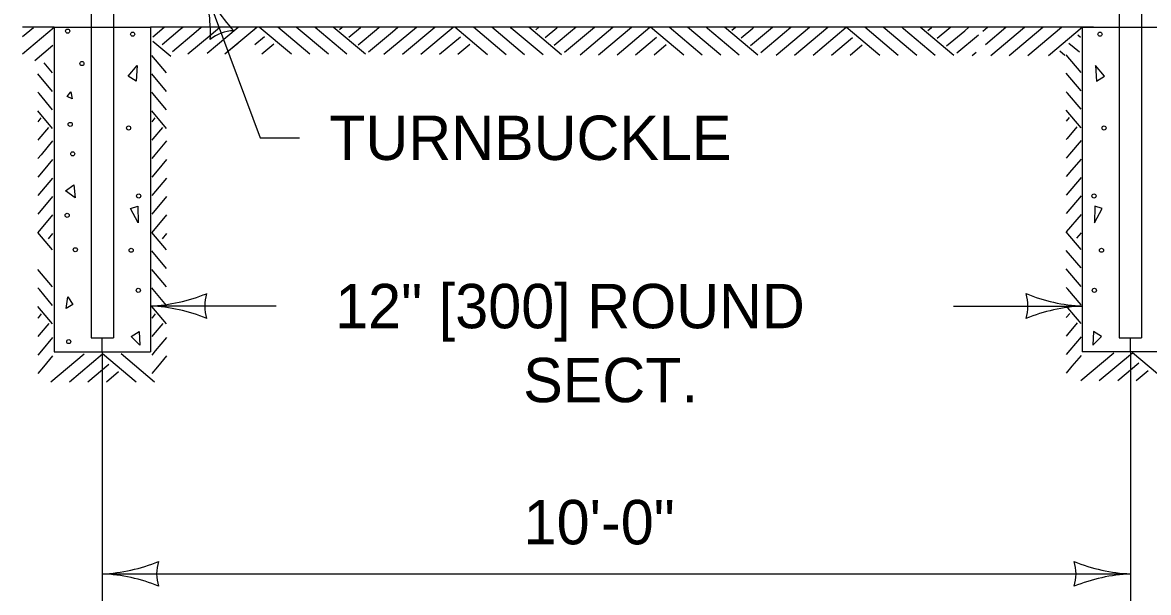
# Model space of a CAD drawing. Extents: x 49973.1 to 50021, y 49987.6 to 50015.4.
# Drawn here: x 50000.781 to 50002.303, y 49991.647 to 49992.418 of the extents above; entities that cross this region are included whole.
import ezdxf

# ---------------------------------------------------------------- set-up
doc = ezdxf.new("R2010")
doc.units = 0
for name, color, linetype in [('Level 1', 7, 'Continuous'), ('Level 2', 7, 'Continuous'), ('Level 3', 7, 'Continuous')]:
    doc.layers.add(name, color=color, linetype=linetype)

msp = doc.modelspace()

# ---------------------------------------------------------------- linework, layer by layer
at = {"layer": 'Level 1'}
for p, q in [((50000.8737, 49992.4466), (50000.8737, 49991.9918)), ((50000.9037, 49992.4466), (50000.9037, 49991.9918)), ((50002.2634, 49992.4418), (50002.2634, 49991.9918)), ((50002.2934, 49992.4418), (50002.2934, 49991.9918)), ((50000.7808, 49992.3757), (50000.8237, 49992.4117)), ((50000.8237, 49992.4117), (50000.7808, 49992.4117)), ((50000.7808, 49992.3992), (50000.7955, 49992.4116)), ((50000.8237, 49992.4118), (50000.8237, 49991.9727)), ((50000.8237, 49992.4118), (50000.9537, 49992.4118)), ((50000.8314, 49992.4117), (50000.8337, 49992.4117)), ((50002.2284, 49992.4118), (50000.9537, 49992.4118)), ((50000.9537, 49992.4118), (50000.9537, 49991.9727)), ((50000.957, 49992.3989), (50000.9724, 49992.4117)), ((50000.9941, 49992.409), (50000.9974, 49992.4117)), ((50001.0157, 49992.4061), (50001.0225, 49992.4117)), ((50001.0304, 49992.3765), (50001.0725, 49992.4117)), ((50001.0358, 49992.4019), (50001.0475, 49992.4117)), ((50001.0543, 49992.3756), (50001.0974, 49992.4117)), ((50001.0917, 49992.4069), (50001.0974, 49992.4117)), ((50001.1444, 49992.3751), (50001.1009, 49992.4117)), ((50001.1694, 49992.3751), (50001.1259, 49992.4117)), ((50001.1944, 49992.3751), (50001.1509, 49992.4117)), ((50001.1764, 49992.4112), (50001.1759, 49992.4117)), ((50001.2194, 49992.3751), (50001.1764, 49992.4112)), ((50001.2444, 49992.3751), (50001.2009, 49992.4117)), ((50001.2094, 49992.4086), (50001.2131, 49992.4117)), ((50001.2221, 49992.3984), (50001.2378, 49992.4115)), ((50001.2378, 49992.4115), (50001.2381, 49992.4117)), ((50001.2592, 49992.4085), (50001.2631, 49992.4117)), ((50001.2694, 49992.3751), (50001.3132, 49992.4117)), ((50001.2808, 49992.4056), (50001.2882, 49992.4117)), ((50001.2944, 49992.3751), (50001.3382, 49992.4117)), ((50001.3194, 49992.3751), (50001.3631, 49992.4117)), ((50001.4095, 49992.3746), (50001.3654, 49992.4117)), ((50001.4345, 49992.3746), (50001.3904, 49992.4117)), ((50001.4595, 49992.3746), (50001.4154, 49992.4117)), ((50001.4415, 49992.4107), (50001.4404, 49992.4117)), ((50001.4845, 49992.3746), (50001.4415, 49992.4107)), ((50001.5095, 49992.3746), (50001.4654, 49992.4117)), ((50001.4745, 49992.4081), (50001.4788, 49992.4117)), ((50001.4872, 49992.3979), (50001.5029, 49992.411)), ((50001.5029, 49992.411), (50001.5038, 49992.4117)), ((50001.5243, 49992.408), (50001.5288, 49992.4117)), ((50001.5345, 49992.3746), (50001.5789, 49992.4117)), ((50001.5459, 49992.4051), (50001.5539, 49992.4117)), ((50001.5595, 49992.3746), (50001.6039, 49992.4117)), ((50001.5845, 49992.3746), (50001.6288, 49992.4117)), ((50001.6746, 49992.3741), (50001.6299, 49992.4117)), ((50001.6996, 49992.3741), (50001.6549, 49992.4117)), ((50001.7246, 49992.3741), (50001.6799, 49992.4117)), ((50001.7066, 49992.4102), (50001.7049, 49992.4117)), ((50001.7496, 49992.3741), (50001.7066, 49992.4102)), ((50001.7746, 49992.3741), (50001.7299, 49992.4117)), ((50001.7396, 49992.4076), (50001.7446, 49992.4118)), ((50001.7523, 49992.3974), (50001.768, 49992.4105)), ((50001.768, 49992.4105), (50001.7695, 49992.4117)), ((50001.7894, 49992.4075), (50001.7945, 49992.4117)), ((50001.7996, 49992.3741), (50001.8446, 49992.4117)), ((50001.811, 49992.4046), (50001.8196, 49992.4117)), ((50001.8246, 49992.3741), (50001.8696, 49992.4117)), ((50001.8496, 49992.3741), (50001.8944, 49992.4117)), ((50001.9397, 49992.3736), (50001.8944, 49992.4117)), ((50001.9647, 49992.3736), (50001.9194, 49992.4117)), ((50001.9897, 49992.3736), (50001.9444, 49992.4117)), ((50001.9717, 49992.4097), (50001.9694, 49992.4117)), ((50002.0147, 49992.3736), (50001.9717, 49992.4097)), ((50002.0397, 49992.3736), (50001.9944, 49992.4117)), ((50002.0047, 49992.4071), (50002.0097, 49992.4113)), ((50002.0097, 49992.4113), (50002.0102, 49992.4117)), ((50002.0174, 49992.3969), (50002.0331, 49992.41)), ((50002.0331, 49992.41), (50002.0352, 49992.4117)), ((50002.0545, 49992.407), (50002.0602, 49992.4117)), ((50002.0788, 49992.4064), (50002.0853, 49992.4117)), ((50002.0825, 49992.3885), (50002.1102, 49992.4117)), ((50002.0897, 49992.3736), (50002.1352, 49992.4117)), ((50002.1147, 49992.3736), (50002.1601, 49992.4117)), ((50002.1397, 49992.3736), (50002.1852, 49992.4117)), ((50002.1679, 49992.3737), (50002.2134, 49992.4118)), ((50002.2134, 49992.4118), (50002.2134, 49991.9727)), ((50002.2134, 49992.4118), (50002.3434, 49992.4118)), ((50000.9695, 49992.3884), (50000.9941, 49992.409)), ((50000.9834, 49992.379), (50001.0157, 49992.4061)), ((50001.0043, 49992.3756), (50001.0358, 49992.4019)), ((50001.0948, 49992.3886), (50001.1077, 49992.3994)), ((50001.2346, 49992.3879), (50001.2592, 49992.4085)), ((50001.2485, 49992.3785), (50001.2808, 49992.4056)), ((50001.3444, 49992.3751), (50001.3728, 49992.3989)), ((50001.4997, 49992.3874), (50001.5243, 49992.408)), ((50001.5136, 49992.378), (50001.5459, 49992.4051)), ((50001.6095, 49992.3746), (50001.6379, 49992.3984)), ((50001.7648, 49992.3869), (50001.7894, 49992.4075)), ((50001.7787, 49992.3775), (50001.811, 49992.4046)), ((50001.8746, 49992.3741), (50001.903, 49992.3979)), ((50002.0299, 49992.3864), (50002.0545, 49992.407)), ((50002.0438, 49992.377), (50002.0731, 49992.4016)), ((50002.2108, 49992.3979), (50002.2073, 49992.4008)), ((50000.7974, 49992.3667), (50000.822, 49992.3873)), ((50000.9814, 49992.372), (50000.9568, 49992.3926)), ((50001.0543, 49992.3756), (50001.0717, 49992.3902)), ((50001.1043, 49992.3756), (50001.1206, 49992.3893)), ((50001.3694, 49992.3751), (50001.3857, 49992.3888)), ((50001.6345, 49992.3746), (50001.6508, 49992.3883)), ((50001.8996, 49992.3741), (50001.9159, 49992.3878)), ((50002.1897, 49992.3736), (50002.1829, 49992.3793)), ((50002.2096, 49992.3779), (50002.1952, 49992.3899)), ((50000.8215, 49992.35), (50000.81, 49992.3637)), ((50000.9755, 49992.35), (50000.9556, 49992.3737)), ((50002.0647, 49992.3736), (50002.07, 49992.3781)), ((50002.2117, 49992.3507), (50002.1918, 49992.3744)), ((50000.8215, 49992.325), (50000.8016, 49992.3487)), ((50000.9755, 49992.325), (50000.9556, 49992.3487)), ((50002.2117, 49992.3257), (50002.1918, 49992.3494)), ((50000.8031, 49992.322), (50000.8016, 49992.3237)), ((50000.8215, 49992.3), (50000.8031, 49992.322)), ((50000.9571, 49992.322), (50000.9556, 49992.3237)), ((50000.9755, 49992.3), (50000.9571, 49992.322)), ((50002.1933, 49992.3227), (50002.1918, 49992.3244)), ((50002.2117, 49992.3007), (50002.1933, 49992.3227)), ((50000.8057, 49992.289), (50000.8015, 49992.284)), ((50000.8215, 49992.275), (50000.8016, 49992.2987)), ((50000.9597, 49992.289), (50000.9555, 49992.284)), ((50000.9755, 49992.275), (50000.9556, 49992.2987)), ((50002.1959, 49992.2897), (50002.1917, 49992.2847)), ((50002.2117, 49992.2757), (50002.1918, 49992.2994)), ((50000.8159, 49992.2763), (50000.8028, 49992.2606)), ((50000.9699, 49992.2763), (50000.9568, 49992.2606)), ((50002.2061, 49992.277), (50002.193, 49992.2613)), ((50000.8028, 49992.2606), (50000.8016, 49992.2591)), ((50000.8215, 49992.2579), (50000.8058, 49992.2392)), ((50000.9568, 49992.2606), (50000.9556, 49992.2591)), ((50000.9755, 49992.2579), (50000.9598, 49992.2392)), ((50002.193, 49992.2613), (50002.1918, 49992.2598)), ((50002.2117, 49992.2586), (50002.196, 49992.2399)), ((50000.8058, 49992.2392), (50000.8016, 49992.2341)), ((50000.8215, 49992.2328), (50000.8087, 49992.2176)), ((50000.9598, 49992.2392), (50000.9556, 49992.2341)), ((50000.9755, 49992.2328), (50000.9627, 49992.2176)), ((50002.196, 49992.2399), (50002.1918, 49992.2348)), ((50002.2117, 49992.2335), (50002.1989, 49992.2183)), ((50000.8087, 49992.2176), (50000.8016, 49992.209)), ((50000.9627, 49992.2176), (50000.9556, 49992.209)), ((50002.1989, 49992.2183), (50002.1918, 49992.2097)), ((50000.8215, 49992.2078), (50000.8016, 49992.184)), ((50000.9755, 49992.2078), (50000.9556, 49992.184)), ((50002.2117, 49992.2085), (50002.1918, 49992.1847)), ((50000.8215, 49992.1828), (50000.8016, 49992.159)), ((50000.9755, 49992.1828), (50000.9556, 49992.159)), ((50002.2117, 49992.1835), (50002.1918, 49992.1597)), ((50000.8215, 49992.1579), (50000.8016, 49992.1342)), ((50000.9755, 49992.1579), (50000.9556, 49992.1342)), ((50002.2117, 49992.1586), (50002.1918, 49992.1349)), ((50000.8215, 49992.1105), (50000.8016, 49992.1342)), ((50000.8215, 49992.1328), (50000.8154, 49992.1256)), ((50000.9755, 49992.1105), (50000.9556, 49992.1342)), ((50000.9755, 49992.1328), (50000.9694, 49992.1256)), ((50002.2117, 49992.1112), (50002.1918, 49992.1349)), ((50002.2117, 49992.1335), (50002.2056, 49992.1263)), ((50000.9755, 49992.0855), (50000.9556, 49992.1092)), ((50002.2117, 49992.0862), (50002.1918, 49992.1099)), ((50000.8215, 49992.0605), (50000.8016, 49992.0842)), ((50000.9755, 49992.0605), (50000.9556, 49992.0842)), ((50002.2117, 49992.0612), (50002.1918, 49992.0849)), ((50000.8036, 49992.0569), (50000.8016, 49992.0592)), ((50000.9576, 49992.0569), (50000.9556, 49992.0592)), ((50002.1938, 49992.0576), (50002.1918, 49992.0599)), ((50000.8215, 49992.0355), (50000.8036, 49992.0569)), ((50000.9755, 49992.0355), (50000.9576, 49992.0569)), ((50002.2117, 49992.0362), (50002.1938, 49992.0576)), ((50000.8215, 49992.0105), (50000.8016, 49992.0342)), ((50000.9755, 49992.0105), (50000.9556, 49992.0342)), ((50002.2117, 49992.0112), (50002.1918, 49992.0349)), ((50000.802, 49992.0189), (50000.8016, 49992.0184)), ((50000.8062, 49992.0239), (50000.802, 49992.0189)), ((50000.956, 49992.0189), (50000.9556, 49992.0184)), ((50000.9602, 49992.0239), (50000.956, 49992.0189)), ((50002.1922, 49992.0196), (50002.1918, 49992.0191)), ((50002.1964, 49992.0246), (50002.1922, 49992.0196)), ((50000.8164, 49992.0112), (50000.8033, 49991.9955)), ((50000.9704, 49992.0112), (50000.9573, 49991.9955)), ((50002.2066, 49992.0119), (50002.1935, 49991.9962)), ((50000.8033, 49991.9955), (50000.8016, 49991.9934)), ((50000.8215, 49991.9922), (50000.8063, 49991.9741)), ((50000.8737, 49991.9918), (50000.9037, 49991.9918)), ((50000.8887, 49991.9918), (50000.8887, 49991.9912)), ((50000.9573, 49991.9955), (50000.9556, 49991.9934)), ((50000.9755, 49991.9922), (50000.9603, 49991.9741)), ((50002.1935, 49991.9962), (50002.1918, 49991.9941)), ((50002.2117, 49991.9929), (50002.1965, 49991.9748)), ((50002.2634, 49991.9918), (50002.2934, 49991.9918)), ((50002.2784, 49991.9918), (50002.2784, 49991.9912)), ((50000.8063, 49991.9741), (50000.8016, 49991.9684)), ((50000.8193, 49991.9322), (50000.8643, 49991.9698)), ((50000.8237, 49991.9727), (50000.9537, 49991.9727)), ((50000.8443, 49991.9322), (50000.8891, 49991.9698)), ((50000.9344, 49991.9317), (50000.8891, 49991.9698)), ((50000.9594, 49991.9317), (50000.9141, 49991.9698)), ((50000.9603, 49991.9741), (50000.9556, 49991.9684)), ((50002.1965, 49991.9748), (50002.1918, 49991.9691)), ((50002.2117, 49991.9678), (50002.1994, 49991.9532)), ((50002.2113, 49991.9339), (50002.2563, 49991.9715)), ((50002.3434, 49991.9727), (50002.2134, 49991.9727)), ((50002.2363, 49991.9339), (50002.2811, 49991.9715)), ((50002.3264, 49991.9334), (50002.2811, 49991.9715)), ((50000.8215, 49991.9671), (50000.8092, 49991.9525)), ((50000.8693, 49991.9322), (50000.8977, 49991.956)), ((50000.9755, 49991.9671), (50000.9632, 49991.9525)), ((50002.1994, 49991.9532), (50002.1918, 49991.944)), ((50002.2613, 49991.9339), (50002.2897, 49991.9577)), ((50000.8092, 49991.9525), (50000.8016, 49991.9433)), ((50000.8943, 49991.9322), (50000.9106, 49991.9459)), ((50000.9632, 49991.9525), (50000.9556, 49991.9433)), ((50002.2863, 49991.9339), (50002.3026, 49991.9476))]:
    msp.add_line(p, q, dxfattribs=at)
for points in [[(50000.9235, 49992.3455), (50000.9359, 49992.3599), (50000.9345, 49992.3387)], [(50002.2436, 49992.3455), (50002.2312, 49992.3599), (50002.2326, 49992.3387)], [(50000.8412, 49992.3181), (50000.846, 49992.3243), (50000.848, 49992.3147)], [(50000.8391, 49992.1905), (50000.8501, 49992.1987), (50000.8522, 49992.1808)], [(50000.9269, 49992.1664), (50000.9365, 49992.1699), (50000.9372, 49992.1472)], [(50002.2402, 49992.1664), (50002.2306, 49992.1699), (50002.2299, 49992.1472)], [(50000.8398, 49992.0313), (50000.8419, 49992.047), (50000.8487, 49992.0368)], [(50000.9276, 49991.9935), (50000.9386, 49992.0004), (50000.9393, 49991.9819)], [(50002.2395, 49991.9935), (50002.2285, 49992.0004), (50002.2278, 49991.9819)]]:
    msp.add_lwpolyline(points, close=True, dxfattribs=at)
for centre in [(50000.8419, 49992.4065), (50000.9297, 49992.4024), (50002.2374, 49992.4024), (50000.8611, 49992.3626), (50000.8453, 49992.2803), (50000.9242, 49992.2755), (50002.2429, 49992.2755), (50000.8487, 49992.2405), (50000.9379, 49992.1835), (50002.2292, 49992.1835), (50000.8412, 49992.1574), (50000.8522, 49992.1108), (50000.9277, 49992.1101), (50002.2394, 49992.1101), (50000.9373, 49992.0559), (50002.2298, 49992.0559), (50000.8433, 49991.9866)]:
    msp.add_circle(centre, 0.00279, dxfattribs=at)
at = {"layer": 'Level 3'}
for p, q in [((50001.0239, 49992.4725), (50001.102, 49992.2622)), ((50001.102, 49992.2622), (50001.1554, 49992.2622)), ((50001.1237, 49992.0346), (50000.9537, 49992.0346)), ((50002.0394, 49992.0346), (50002.2134, 49992.0346)), ((50000.8887, 49991.9727), (50000.8887, 49991.9912)), ((50002.2784, 49991.9727), (50002.2784, 49991.9912)), ((50000.8887, 49991.9727), (50000.8887, 49991.6324)), ((50002.2784, 49991.9727), (50002.2784, 49991.6324)), ((50000.8887, 49991.6724), (50002.2784, 49991.6724))]:
    msp.add_line(p, q, dxfattribs=at)
for centre, radius, start, end in [((50000.8125, 49992.4037), 0.2223, 357.8356, 18.0191), ((50001.238, 49992.5643), 0.233, 203.2069, 222.4568), ((50001.0685, 49992.3523), 0.0548, 92.5184, 128.2408), ((50000.9422, 49992.2673), 0.233, 272.8273, 292.0772), ((50001.0819, 49992.0346), 0.0548, 162.1388, 197.8612), ((50002.2226, 49992.2568), 0.2223, 247.456, 267.6395), ((50002.0852, 49992.0346), 0.0548, 342.1388, 17.8612), ((50000.9446, 49991.8125), 0.2223, 67.456, 87.6395), ((50002.2249, 49991.8019), 0.233, 92.8273, 112.0772), ((50000.8772, 49991.9051), 0.233, 272.8273, 292.0772), ((50001.0169, 49991.6724), 0.0548, 162.1388, 197.8612), ((50002.2876, 49991.8946), 0.2223, 247.456, 267.6395), ((50002.1502, 49991.6724), 0.0548, 342.1388, 17.8612), ((50000.8796, 49991.4503), 0.2223, 67.456, 87.6395), ((50002.2899, 49991.4397), 0.233, 92.8273, 112.0772)]:
    msp.add_arc(centre, radius, start, end, dxfattribs=at)

# ---------------------------------------------------------------- texts
at = {"layer": 'Level 2'}
for s, p in [('TURNBUCKLE', (50001.1954, 49992.2322)), ('12" [300] ROUND', (50001.2034, 49992.0046)), ('SECT.', (50001.4576, 49991.9046)), ('10\'-0"', (50001.4582, 49991.7124))]:
    msp.add_text(s, height=0.06, dxfattribs=at).set_placement(p)

doc.saveas('drawing.dxf')
